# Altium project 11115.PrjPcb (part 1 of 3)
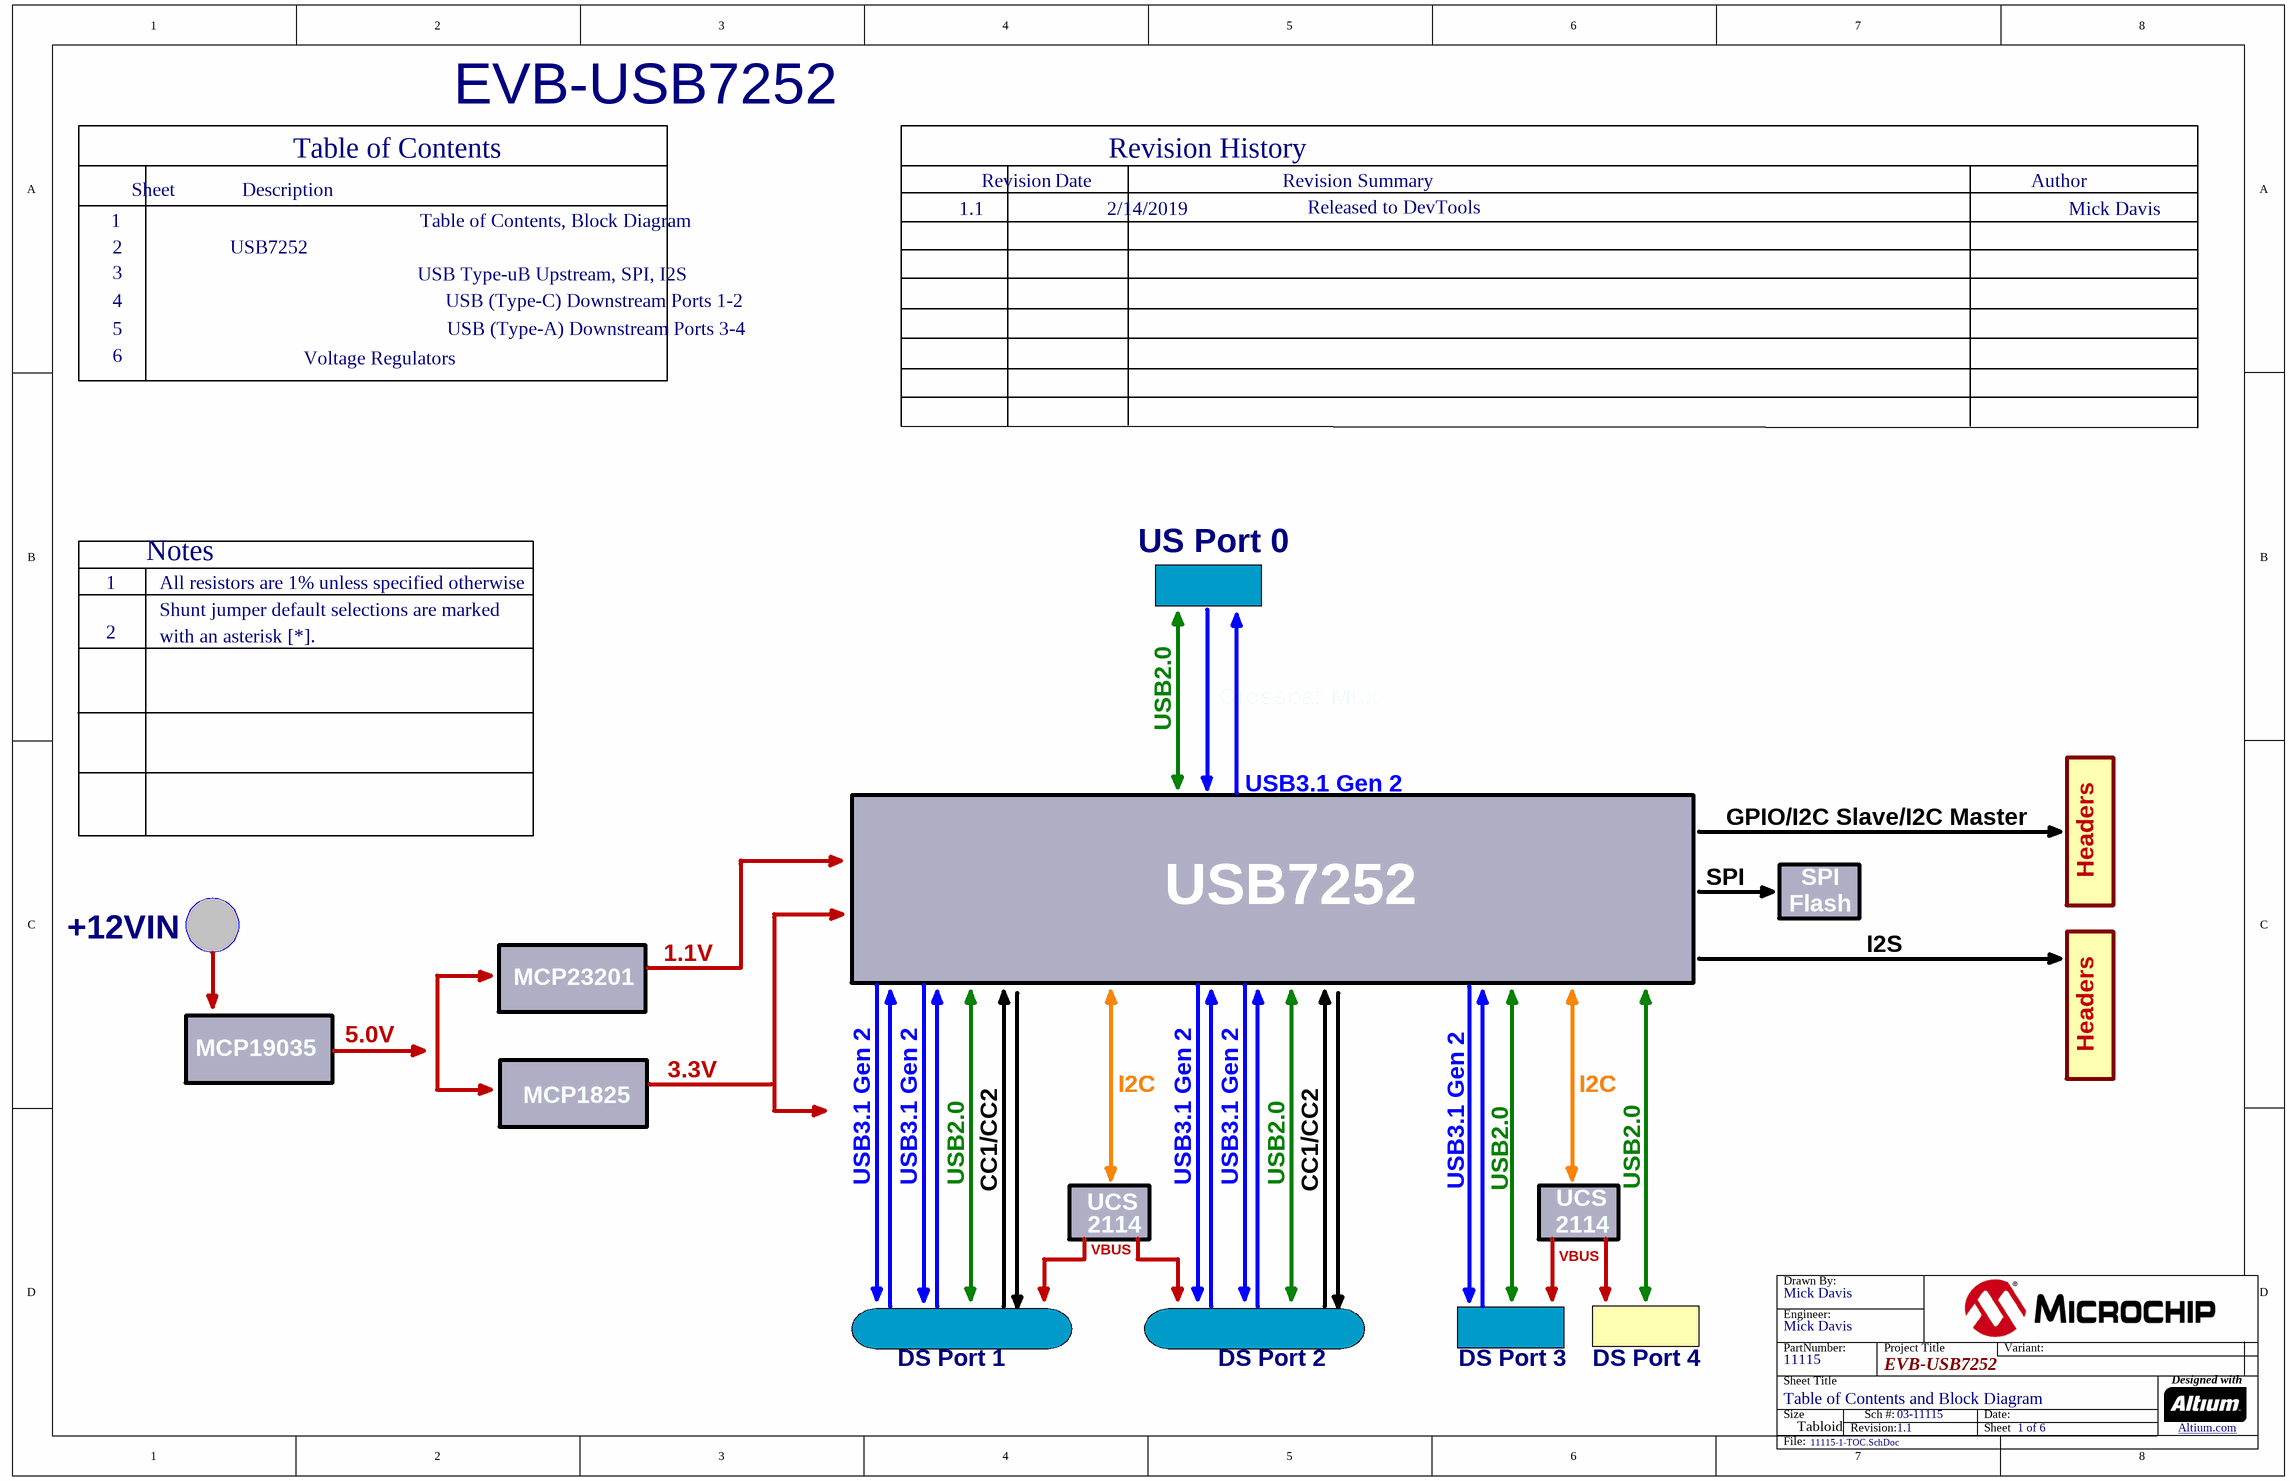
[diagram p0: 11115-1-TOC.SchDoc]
ProjectPCBNumber: 11115; SheetTotal: 6; Revision: 1.1; ProjectTitle: EVB-USB7252; ProjectRevisionSCH: 1.1; ProjectRevisionFAB: 1.1; ProjectRevisionASSY: 1.1; ProjectRevisionART: 1.1; ProjectPCBAssyNumber: 11115; ProjectPartNumber: 11115; ProjectEngineer: Mick Davis; ProjectDrawnBy: Mick Davis; ProjectBoardNumber: 11115; ProjectBoardLabel: 11115; PartNumber: 11115
6 sheets, 332 parts. Net scope: flat (ports and power ports of the same name join across sheets).
Board file: 11115.PcbDoc
Sheets:
  11115-1-TOC.SchDoc
  11115-2-USB7252.SchDoc
  11115-3-USB-B-Upstream.SchDoc
  11115-4-USB-C Downstream 1-2.SchDoc
  11115-5-USB-A Downstream 3-4.SchDoc
  11115-6-Voltage_Regulators.SchDoc

## Sheet 11115-1-TOC.SchDoc
size Tabloid; CompanyName: Microchip Technology Inc.; Organization: Microchip Technology; Address1: 2355 West Chandler Blvd.; Address2: Chandler, AZ  85224; Address4: USA; Revision: 1.0; SheetNumber: 1; SheetTotal: 6; SheetTitle: Table of Contents and Block Diagram

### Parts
(Parts that share a designator on the sheet are numbered #1, #2 ... from top to bottom, then left to right.)
?#1  (no value)  (graphical)

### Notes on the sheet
- Table of Contents
- Revision History
- 1
- Sheet
- Description
- Table of Contents, Block Diagram
- 1.1
- Revision
- Date
- 2/14/2019
- Revision Summary
- Released to DevTools
- Author
- Mick Davis
- 2
- 3
- USB7252
- USB Type-uB Upstream, SPI, I2S
- 4
- 5
- 6
- Voltage Regulators
- USB (Type-C) Downstream Ports 1-2
- USB (Type-A) Downstream Ports 3-4
- Notes
- US Port 0
- All resistors are 1% unless specified otherwise
- Shunt jumper default selections are marked
- with an asterisk [*].
- USB2.0
- Crossbar Mux
- USB3.1 Gen 2
- GPIO/I2C Slave/I2C Master
- SPI
- Headers
- +12VIN
- 1.1V
- Flash
- I2S
- MCP23201
- MCP19035
- 5.0V
- 3.3V
- I2C
- MCP1825
- CC1/CC2
- UCS
- 2114
- VBUS
- DS Port 1
- DS Port 2
- DS Port 3
- DS Port 4

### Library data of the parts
?#1 = Title Block Tabloid

## Sheet 11115-2-USB7252.SchDoc
size Tabloid; CompanyName: Microchip Technology Inc.; Organization: Microchip Technology; Address1: 2355 West Chandler Blvd.; Address2: Chandler, AZ  85224; Address4: USA; SheetNumber: 2; SheetTotal: 6; SheetTitle: USB7252
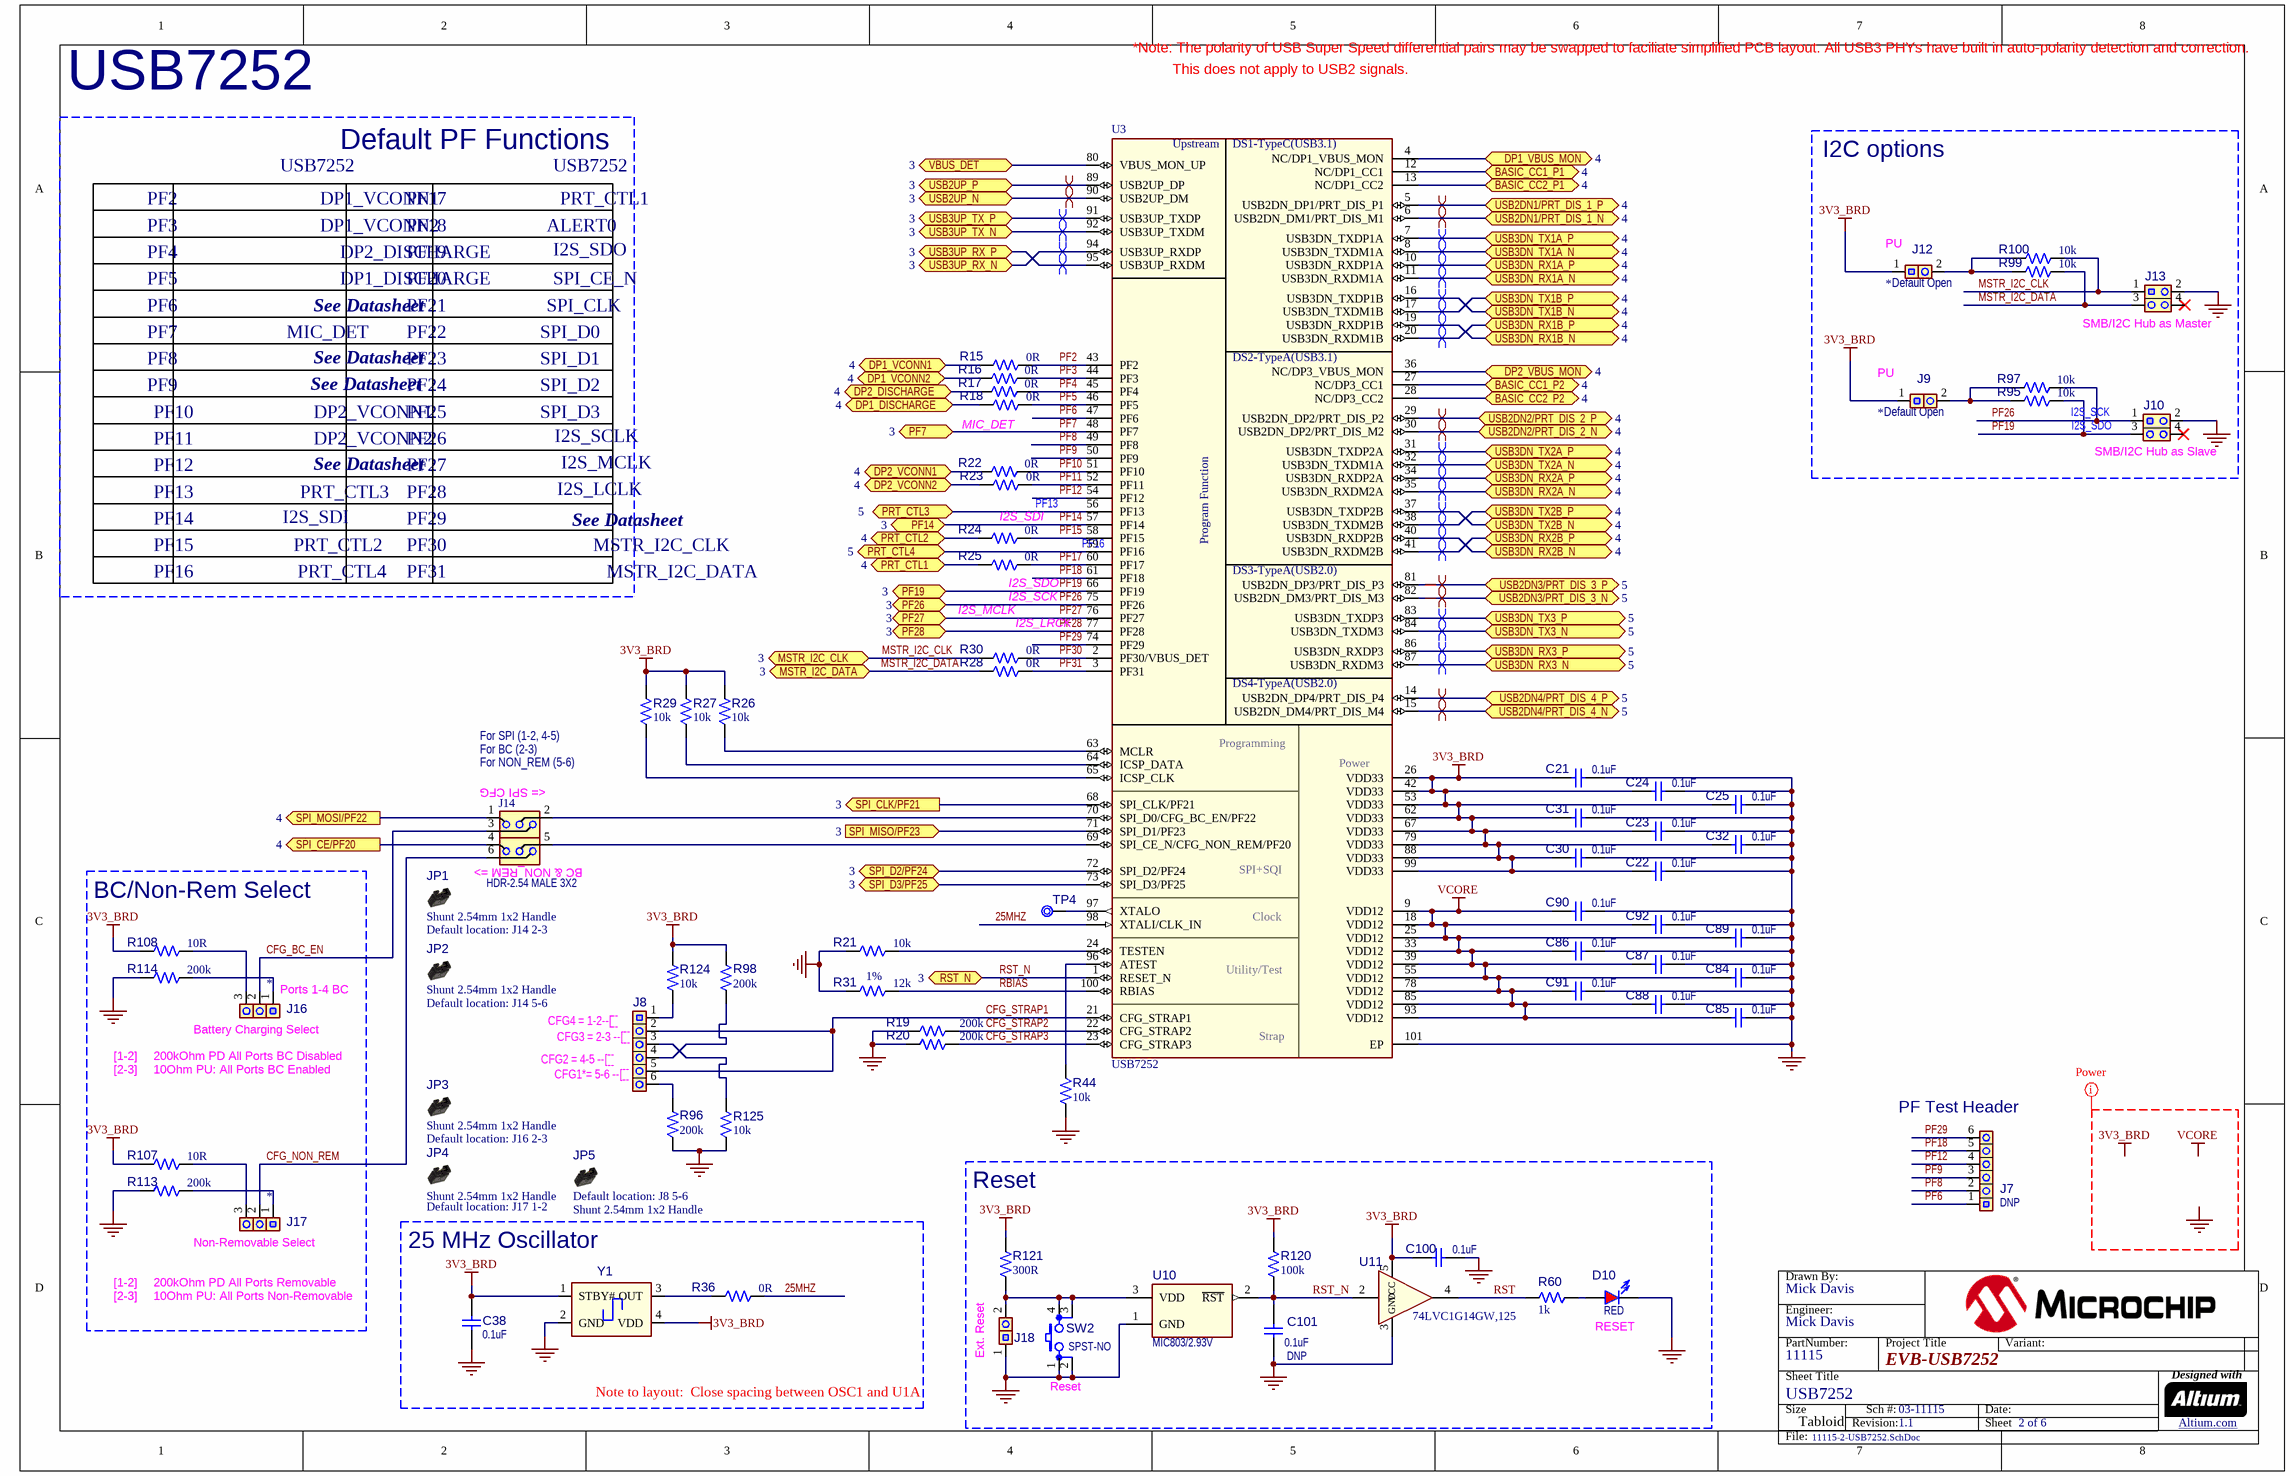
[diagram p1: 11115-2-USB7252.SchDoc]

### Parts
(Parts that share a designator on the sheet are numbered #1, #2 ... from top to bottom, then left to right.)
?#2  (no value)  (graphical)
C21  value 0.1uF  [CAP_C_0402]  (hidden comment: Capacitor NP)
C22  value 0.1uF  [CAP_C_0402]  (hidden comment: Capacitor NP)
C23  value 0.1uF  [CAP_C_0402]  (hidden comment: Capacitor NP)
C24  value 0.1uF  [CAP_C_0402]  (hidden comment: Capacitor NP)
C25  value 0.1uF  [CAP_C_0402]  (hidden comment: Capacitor NP)
C30  value 0.1uF  [CAP_C_0402]  (hidden comment: Capacitor NP)
C31  value 0.1uF  [CAP_C_0402]  (hidden comment: Capacitor NP)
C32  value 0.1uF  [CAP_C_0402]  (hidden comment: Capacitor NP)
C38  value 0.1uF  [CAP_C_0402]  (hidden comment: Capacitor NP)
C84  value 0.1uF  [CAP_C_0402]  (hidden comment: Capacitor NP)
C85  value 0.1uF  [CAP_C_0402]  (hidden comment: Capacitor NP)
C86  value 0.1uF  [CAP_C_0402]  (hidden comment: Capacitor NP)
C87  value 0.1uF  [CAP_C_0402]  (hidden comment: Capacitor NP)
C88  value 0.1uF  [CAP_C_0402]  (hidden comment: Capacitor NP)
C89  value 0.1uF  [CAP_C_0402]  (hidden comment: Capacitor NP)
C90  value 0.1uF  [CAP_C_0402]  (hidden comment: Capacitor NP)
C91  value 0.1uF  [CAP_C_0402]  (hidden comment: Capacitor NP)
C92  value 0.1uF  [CAP_C_0402]  (hidden comment: Capacitor NP)
C100  value 0.1uF  [CAP_C_0402]  (hidden comment: Capacitor NP)
C101  value 0.1uF  Populated: DNP  [CAP_C_0402]  (hidden comment: Capacitor NP)
D10  value RED  [LED_0603_RED]  (hidden comment: LED_red)
J7  Populated: DNP  [HDR_M_2.54_1x6]  (hidden comment: Header 1x6)
J8  Header 1x6  [HDR_M_2.54_1x6]  (value not drawn)
J9  Header 1x2  [HDR_M_2.54_1x2]  (value not drawn)
J10  Header 2x2  [HDR_M_2.54_2x2]  (value not drawn)
J12  Header 1x2  [HDR_M_2.54_1x2]  (value not drawn)
J13  Header 2x2  [HDR_M_2.54_2x2]  (value not drawn)
J14  value HDR-2.54 MALE 3X2  [CON_HDR_2.54_3X2]  (hidden comment: Header 3X2)
J16  Header 1x3  [HDR_M_2.54_1x3]  (value not drawn)
J17  Header 1x3  [HDR_M_2.54_1x3]  (value not drawn)
J18  Header 1x2  [HDR_M_2.54_1x2]  (value not drawn)
JP1  value Shunt 2.54mm 1x2 Handle  DefaultLocation: Default location: J14 2-3  [Jumper_W_Handle_Mechanical]  (hidden comment: Jumper Mechanical)  (mechanical)
JP2  value Shunt 2.54mm 1x2 Handle  DefaultLocation: Default location: J14 5-6  [Jumper_W_Handle_Mechanical]  (hidden comment: Jumper Mechanical)  (mechanical)
JP3  value Shunt 2.54mm 1x2 Handle  DefaultLocation: Default location: J16 2-3  [Jumper_W_Handle_Mechanical]  (hidden comment: Jumper Mechanical)  (mechanical)
JP4  value Shunt 2.54mm 1x2 Handle  DefaultLocation: Default location: J17 1-2  [Jumper_W_Handle_Mechanical]  (hidden comment: Jumper Mechanical)  (mechanical)
JP5  value Shunt 2.54mm 1x2 Handle  DefaultLocation: Default location: J8 5-6  [Jumper_W_Handle_Mechanical]  (hidden comment: Jumper Mechanical)  (mechanical)
R15  0R  [RES_C_0603]
R16  0R  [RES_C_0603]
R17  0R  [RES_C_0603]
R18  0R  [RES_C_0603]
R19  value 200k  [RES_C_0603]  (hidden comment: Resistor)
R20  value 200k  [RES_C_0603]  (hidden comment: Resistor)
R21  value 10k  [RES_C_0603]  (hidden comment: Resistor)
R22  0R  [RES_C_0603]
R23  0R  [RES_C_0603]
R24  0R  [RES_C_0603]
R25  0R  [RES_C_0603]
R26  value 10k  [RES_C_0603]  (hidden comment: Resistor)
R27  value 10k  [RES_C_0603]  (hidden comment: Resistor)
R28  0R  [RES_C_0603]
R29  value 10k  [RES_C_0603]  (hidden comment: Resistor)
R30  0R  [RES_C_0603]
R31  value 12k  Tolerance: 1%  [RES_C_0603]  (hidden comment: Resistor)
R36  value 0R  [RES_C_0603]  (hidden comment: Resistor)
R44  value 10k  [RES_C_0603]  (hidden comment: Resistor)
R60  value 1k  [RES_C_0603]  (hidden comment: Resistor)
R95  value 10k  [RES_C_0603]  (hidden comment: Resistor)
R96  value 200k  [RES_C_0603]  (hidden comment: Resistor)
R97  value 10k  [RES_C_0603]  (hidden comment: Resistor)
R98  value 200k  [RES_C_0603]  (hidden comment: Resistor)
R99  value 10k  [RES_C_0603]  (hidden comment: Resistor)
R100  value 10k  [RES_C_0603]  (hidden comment: Resistor)
R107  value 10R  [RES_C_0603]  (hidden comment: Resistor)
R108  value 10R  [RES_C_0603]  (hidden comment: Resistor)
R113  value 200k  [RES_C_0603]  (hidden comment: Resistor)
R114  value 200k  [RES_C_0603]  (hidden comment: Resistor)
R120  value 100k  [RES_C_0603]  (hidden comment: Resistor)
R121  value 300R  [RES_C_0603]  (hidden comment: Resistor)
R124  value 10k  [RES_C_0603]  (hidden comment: Resistor)
R125  value 10k  [RES_C_0603]  (hidden comment: Resistor)
SW2  value SPST-NO  [SW_TACT_SMD_CK_PTS810SJM]  (hidden comment: Switch 4 Pin)
TP4  Test Point No BOM  [CON_TP_22P11_TH]  (value not drawn)  (no BOM)
U3  value USB7252  [TQFN-100_12x12_EP8.0]  (hidden comment: USB7252 VQFN-100)
U10  value MIC803/2.93V  [SOT-23-3]  (hidden comment: MIC803 SOT-23-3)
U11  74LVC1G14GW,125  [SC-70-5]
Y1  OSCILLATOR_4P_nSTBY  [OSCILLATOR_CDFN_L2.5W2.0H0.85]  (value not drawn)

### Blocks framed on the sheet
I2C options: J9 J10 J12 J13 R95 R97 R99 R100
BC/Non-Rem Select: J16 J17 R107 R108 R113 R114
Reset: C100 C101 D10 J18 R60 R120 R121 SW2 U10 U11
25 MHz Oscillator: C38 R36 Y1

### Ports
BASIC_CC1_P1 (bidir, see 4), BASIC_CC1_P2 (bidir, see 4), BASIC_CC2_P1 (bidir, see 4), BASIC_CC2_P2 (bidir, see 4), DP1_DISCHARGE (bidir, see 4), DP1_VBUS_MON (bidir, see 4), DP1_VCONN1 (bidir, see 4), DP1_VCONN2 (bidir, see 4), DP2_DISCHARGE (bidir, see 4), DP2_VBUS_MON (bidir, see 4), DP2_VCONN1 (bidir, see 4), DP2_VCONN2 (bidir, see 4), MSTR_I2C_CLK (bidir, see 3), MSTR_I2C_DATA (bidir, see 3), PF7 (bidir, see 3), PF14 (bidir, see 3), PF19 (bidir, see 3), PF26 (bidir, see 3), PF27 (bidir, see 3), PF28 (bidir, see 3), PRT_CTL1 (bidir, see 4), PRT_CTL2 (bidir, see 4), PRT_CTL3 (bidir, see 5), PRT_CTL4 (bidir, see 5), RST_N (bidir, see 3), SPI_CE/PF20 (out, see 4), SPI_CLK/PF21 (out, see 3), SPI_D2/PF24 (bidir, see 3), SPI_D3/PF25 (bidir, see 3), SPI_MISO/PF23 (in, see 3), SPI_MOSI/PF22 (out, see 4), USB2DN1/PRT_DIS_1_N (bidir, see 4), USB2DN1/PRT_DIS_1_P (bidir, see 4), USB2DN2/PRT_DIS_2_N (bidir, see 4), USB2DN2/PRT_DIS_2_P (bidir, see 4), USB2DN3/PRT_DIS_3_N (bidir, see 5), USB2DN3/PRT_DIS_3_P (bidir, see 5), USB2DN4/PRT_DIS_4_N (bidir, see 5), USB2DN4/PRT_DIS_4_P (bidir, see 5), USB2UP_N (bidir, see 3), USB2UP_P (bidir, see 3), USB3DN_RX1A_N (bidir, see 4), USB3DN_RX1A_P (bidir, see 4), USB3DN_RX1B_N (bidir, see 4), USB3DN_RX1B_P (bidir, see 4), USB3DN_RX2A_N (bidir, see 4), USB3DN_RX2A_P (bidir, see 4), USB3DN_RX2B_N (bidir, see 4), USB3DN_RX2B_P (bidir, see 4), USB3DN_RX3_N (bidir, see 5), USB3DN_RX3_P (bidir, see 5), USB3DN_TX1A_N (bidir, see 4), USB3DN_TX1A_P (bidir, see 4), USB3DN_TX1B_N (bidir, see 4), USB3DN_TX1B_P (bidir, see 4), USB3DN_TX2A_N (bidir, see 4), USB3DN_TX2A_P (bidir, see 4), USB3DN_TX2B_N (bidir, see 4), USB3DN_TX2B_P (bidir, see 4), USB3DN_TX3_N (bidir, see 5), USB3DN_TX3_P (bidir, see 5), USB3UP_RX_N (bidir, see 3), USB3UP_RX_P (bidir, see 3), USB3UP_TX_N (bidir, see 3), USB3UP_TX_P (bidir, see 3), VBUS_DET (bidir, see 3)

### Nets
3V3_BRD: C21.1 C22.1 C23.1 C24.1 C25.1 C30.1 C31.1 C32.1 C38.2 C100.1 J9.1 J12.1 R26.2 R27.2 R29.2 R98.1 R107.1 R108.1 R120.2 R121.2 R124.1 U3.26(VDD33) U3.42(VDD33) U3.53(VDD33) U3.62(VDD33) U3.67(VDD33) U3.79(VDD33) U3.88(VDD33) U3.99(VDD33) U11.5(VCC) Y1.1(STBY#) Y1.4(VDD)
GND: C21.2 C22.2 C23.2 C24.2 C25.2 C30.2 C31.2 C32.2 C38.1 C84.2 C85.2 C86.2 C87.2 C88.2 C89.2 C90.2 C91.2 C92.2 C100.2 C101.1 D10.2(K) J10.2 J13.2 J18.1 R19.2 R20.2 R21.2 R31.1 R44.2 R96.2 R113.1 R114.1 R125.2 SW2.1 SW2.2 U3.101(EP) U10.1(GND) U11.3(GND) Y1.2(GND)
VCORE: C84.1 C85.1 C86.1 C87.1 C88.1 C89.1 C90.1 C91.1 C92.1 U3.9(VDD12) U3.18(VDD12) U3.25(VDD12) U3.33(VDD12) U3.39(VDD12) U3.55(VDD12) U3.78(VDD12) U3.85(VDD12) U3.93(VDD12)
25MHZ: R36.2 U3.98(XTALI/CLK_IN)
BASIC_CC1_P1: U3.12(NC/DP1_CC1) ; port BASIC_CC1_P1
BASIC_CC1_P2: U3.27(NC/DP3_CC1) ; port BASIC_CC1_P2
BASIC_CC2_P1: U3.13(NC/DP1_CC2) ; port BASIC_CC2_P1
BASIC_CC2_P2: U3.28(NC/DP3_CC2) ; port BASIC_CC2_P2
CFG_BC_EN: J14.3 J16.2
CFG_NON_REM: J14.6 J17.2
CFG_STRAP1: J8.2 J8.5 U3.21(CFG_STRAP1)
CFG_STRAP2: R19.1 U3.22(CFG_STRAP2)
CFG_STRAP3: R20.1 U3.23(CFG_STRAP3)
DP1_DISCHARGE: R18.1 ; port DP1_DISCHARGE
DP1_VBUS_MON: U3.4(NC/DP1_VBUS_MON) ; port DP1_VBUS_MON
DP1_VCONN1: R15.1 ; port DP1_VCONN1
DP1_VCONN2: R16.1 ; port DP1_VCONN2
DP2_DISCHARGE: R17.1 ; port DP2_DISCHARGE
DP2_VBUS_MON: U3.36(NC/DP3_VBUS_MON) ; port DP2_VBUS_MON
DP2_VCONN1: R22.1 ; port DP2_VCONN1
DP2_VCONN2: R23.1 ; port DP2_VCONN2
MSTR_I2C_CLK: J13.1 R30.1 R100.1 ; port MSTR_I2C_CLK
MSTR_I2C_DATA: J13.3 R28.1 R99.1 ; port MSTR_I2C_DATA
PF2: R15.2 U3.43(PF2)
PF3: R16.2 U3.44(PF3)
PF4: R17.2 U3.45(PF4)
PF5: R18.2 U3.46(PF5)
PF6: J7.1 U3.47(PF6)
PF7: U3.48(PF7) ; port PF7
PF8: J7.2 U3.49(PF8)
PF9: J7.3 U3.50(PF9)
PF10: R22.2 U3.51(PF10)
PF11: R23.2 U3.52(PF11)
PF12: J7.4 U3.54(PF12)
PF14: U3.57(PF14) ; port PF14
PF15: R24.2 U3.58(PF15)
PF17: R25.2 U3.60(PF17)
PF18: J7.5 U3.61(PF18)
PF19: J10.3 R95.1 U3.66(PF19) ; port PF19
PF26: J10.1 R97.1 U3.75(PF26) ; port PF26
PF27: U3.76(PF27) ; port PF27
PF28: U3.77(PF28) ; port PF28
PF29: J7.6 U3.74(PF29)
PF30: R30.2 U3.2(PF30/VBUS_DET)
PF31: R28.2 U3.3(PF31)
PRT_CTL1: R25.1 ; port PRT_CTL1
PRT_CTL2: R24.1 ; port PRT_CTL2
PRT_CTL3: U3.56(PF13) ; port PRT_CTL3
PRT_CTL4: U3.59(PF16) ; port PRT_CTL4
RBIAS: R31.2 U3.100(RBIAS)
RST: R60.1 U11.4(Y)
RST_N: C101.2 R120.1 U3.1(RESET_N) U10.2(~{RST}) U11.2(A) ; port RST_N
SPI_CE/PF20: J14.4 ; port SPI_CE/PF20
SPI_CLK/PF21: U3.68(SPI_CLK/PF21) ; port SPI_CLK/PF21
SPI_D2/PF24: U3.72(SPI_D2/PF24) ; port SPI_D2/PF24
SPI_D3/PF25: U3.73(SPI_D3/PF25) ; port SPI_D3/PF25
SPI_MISO/PF23: U3.71(SPI_D1/PF23) ; port SPI_MISO/PF23
SPI_MOSI/PF22: J14.1 ; port SPI_MOSI/PF22
USB2DN1/PRT_DIS_1_N: U3.6(USB2DN_DM1/PRT_DIS_M1) ; port USB2DN1/PRT_DIS_1_N
USB2DN1/PRT_DIS_1_P: U3.5(USB2DN_DP1/PRT_DIS_P1) ; port USB2DN1/PRT_DIS_1_P
USB2DN2/PRT_DIS_2_N: U3.30(USB2DN_DP2/PRT_DIS_M2) ; port USB2DN2/PRT_DIS_2_N
USB2DN2/PRT_DIS_2_P: U3.29(USB2DN_DP2/PRT_DIS_P2) ; port USB2DN2/PRT_DIS_2_P
USB2DN3/PRT_DIS_3_N: U3.82(USB2DN_DM3/PRT_DIS_M3) ; port USB2DN3/PRT_DIS_3_N
USB2DN3/PRT_DIS_3_P: U3.81(USB2DN_DP3/PRT_DIS_P3) ; port USB2DN3/PRT_DIS_3_P
USB2DN4/PRT_DIS_4_N: U3.15(USB2DN_DM4/PRT_DIS_M4) ; port USB2DN4/PRT_DIS_4_N
USB2DN4/PRT_DIS_4_P: U3.14(USB2DN_DP4/PRT_DIS_P4) ; port USB2DN4/PRT_DIS_4_P
USB2UP_N: U3.90(USB2UP_DM) ; port USB2UP_N
USB2UP_P: U3.89(USB2UP_DP) ; port USB2UP_P
USB3DN_RX1A_N: U3.11(USB3DN_RXDM1A) ; port USB3DN_RX1A_N
USB3DN_RX1A_P: U3.10(USB3DN_RXDP1A) ; port USB3DN_RX1A_P
USB3DN_RX1B_N: U3.19(USB3DN_RXDP1B) ; port USB3DN_RX1B_N
USB3DN_RX1B_P: U3.20(USB3DN_RXDM1B) ; port USB3DN_RX1B_P
USB3DN_RX2A_N: U3.35(USB3DN_RXDM2A) ; port USB3DN_RX2A_N
USB3DN_RX2A_P: U3.34(USB3DN_RXDP2A) ; port USB3DN_RX2A_P
USB3DN_RX2B_N: U3.40(USB3DN_RXDP2B) ; port USB3DN_RX2B_N
USB3DN_RX2B_P: U3.41(USB3DN_RXDM2B) ; port USB3DN_RX2B_P
USB3DN_RX3_N: U3.87(USB3DN_RXDM3) ; port USB3DN_RX3_N
USB3DN_RX3_P: U3.86(USB3DN_RXDP3) ; port USB3DN_RX3_P
USB3DN_TX1A_N: U3.8(USB3DN_TXDM1A) ; port USB3DN_TX1A_N
USB3DN_TX1A_P: U3.7(USB3DN_TXDP1A) ; port USB3DN_TX1A_P
USB3DN_TX1B_N: U3.16(USB3DN_TXDP1B) ; port USB3DN_TX1B_N
USB3DN_TX1B_P: U3.17(USB3DN_TXDM1B) ; port USB3DN_TX1B_P
USB3DN_TX2A_N: U3.32(USB3DN_TXDM1A) ; port USB3DN_TX2A_N
USB3DN_TX2A_P: U3.31(USB3DN_TXDP2A) ; port USB3DN_TX2A_P
USB3DN_TX2B_N: U3.37(USB3DN_TXDP2B) ; port USB3DN_TX2B_N
USB3DN_TX2B_P: U3.38(USB3DN_TXDM2B) ; port USB3DN_TX2B_P
USB3DN_TX3_N: U3.84(USB3DN_TXDM3) ; port USB3DN_TX3_N
USB3DN_TX3_P: U3.83(USB3DN_TXDP3) ; port USB3DN_TX3_P
USB3UP_RX_N: U3.94(USB3UP_RXDP) ; port USB3UP_RX_N
USB3UP_RX_P: U3.95(USB3UP_RXDM) ; port USB3UP_RX_P
USB3UP_TX_N: U3.92(USB3UP_TXDM) ; port USB3UP_TX_N
USB3UP_TX_P: U3.91(USB3UP_TXDP) ; port USB3UP_TX_P
VBUS_DET: U3.80(VBUS_MON_UP) ; port VBUS_DET
NetD10_1: D10.1(A) R60.2
NetJ8_1: J8.1 R124.2
NetJ8_3: J8.3 R125.1
NetJ8_4: J8.4 R98.2
NetJ8_6: J8.6 R96.1
NetJ9_2: J9.2 R95.2 R97.2
NetJ12_2: J12.2 R99.2 R100.2
NetJ14_2: J14.2 U3.70(SPI_D0/CFG_BC_EN/PF22)
NetJ14_5: J14.5 U3.69(SPI_CE_N/CFG_NON_REM/PF20)
NetJ16_1: J16.1 R114.2
NetJ16_3: J16.3 R108.2
NetJ17_1: J17.1 R113.2
NetJ17_3: J17.3 R107.2
NetJ18_2: J18.2 R121.1 SW2.3 SW2.4 U10.3(VDD)
NetR21_1: R21.1 U3.24(TESTEN)
NetR26_1: R26.1 U3.63(MCLR)
NetR27_1: R27.1 U3.64(ICSP_DATA)
NetR29_1: R29.1 U3.65(ICSP_CLK)
NetR36_1: R36.1 Y1.3(OUT)
NetR44_1: R44.1 U3.96(ATEST)
NetTP4_1: TP4.1 U3.97(XTALO)

Not connected (* = marked no-connect by the designer): J10 4*; J13 4*; U11 1(NC)

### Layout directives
differential pair; net class USB3.: USB3DN_RX1A_N, USB3DN_RX1A_P, USB3DN_RX1B_N, USB3DN_RX1B_P, USB3DN_RX2A_N, USB3DN_RX2A_P, USB3DN_RX2B_N, USB3DN_RX2B_P, USB3DN_RX3_N, USB3DN_RX3_P, USB3DN_TX1A_N, USB3DN_TX1A_P, USB3DN_TX1B_N, USB3DN_TX1B_P, USB3DN_TX2A_N, USB3DN_TX2A_P, USB3DN_TX2B_N, USB3DN_TX2B_P, USB3DN_TX3_N, USB3DN_TX3_P, USB3UP_RX_N, USB3UP_RX_P, USB3UP_TX_N, USB3UP_TX_P
differential pair; net class USB2.: USB2DN1/PRT_DIS_1_N, USB2DN1/PRT_DIS_1_P, USB2DN2/PRT_DIS_2_N, USB2DN2/PRT_DIS_2_P, USB2DN3/PRT_DIS_3_N, USB2DN3/PRT_DIS_3_P, USB2DN4/PRT_DIS_4_N, USB2DN4/PRT_DIS_4_P, USB2UP_N, USB2UP_P
net class Power: 3V3_BRD, GND, VCORE

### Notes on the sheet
- USB7252
- *Note: The polarity of USB Super Speed differential pairs may be swapped to faciliate simplified PCB layout. All USB3 PHYs have built in auto-polarity detection and correction.
- This does not apply to USB2 signals.
- Default PF Functions
- PF3
- PF2
- DP1_VCONN1
- DP1_VCONN2
- PF17
- PF18
- ALERT0
- PRT_CTL1
- PF4
- PF5
- DP2_DISCHARGE
- DP1_DISCHARGE
- PF19
- PF20
- SPI_CE_N
- I2S_SDO
- (near J12) PU
- (near J12) *
- (near J12) Default Open
- PF7
- PF8
- PF6
- MIC_DET
- See Datasheet
- PF21
- PF23
- PF22
- SPI_D0
- SPI_D1
- SPI_CLK
- (near J13) SMB/I2C Hub as Master
- PF9
- PF10
- DP2_VCONN1
- PF24
- PF25
- SPI_D2
- SPI_D3
- (near R18) MIC_DET
- (near J9) PU
- (near J9) *
- (near J9) Default Open
- (near R95) I2S_SCK
- PF11
- PF12
- PF13
- PRT_CTL3
- DP2_VCONN2
- PF26
- PF27
- PF28
- I2S_SCLK
- I2S_LCLK
- I2S_MCLK
- (near J10) SMB/I2C Hub as Slave
- PF15
- PF14
- I2S_SDI
- PRT_CTL2
- PF30
- PF29
- MSTR_I2C_CLK
- (near R24) I2S_SDI
- PF16
- PRT_CTL4
- PF31
- MSTR_I2C_DATA
- (near R25) I2S_SCK
- (near R25) I2S_SDO
- I2S_LRCK
- For SPI (1-2, 4-5)
- For BC (2-3)
- For NON_REM (5-6)
- (near J14) <= SPI CFG
- (near J14) BC & NON_REM =>
- (near J16) *
- (near J16) Ports 1-4 BC
- (near J8) CFG4 = 1-2--[
- (near J8) --
- [1-2]
- [2-3]
- 10Ohm PU: All Ports BC Enabled
- 200kOhm PD All Ports BC Disabled
- (near J16) Battery Charging Select
- (near J8) CFG2 = 4-5 --[
- (near J8) CFG1*= 5-6 --[
- (near J8) CFG3 = 2-3 --[
- (near J7) PF Test Header
- (near J17) *
- 200kOhm PD All Ports Removable
- (near J17) Non-Removable Select
- 10Ohm PU: All Ports Non-Removable
- Ext. Reset
- RESET
- Note to layout:  Close spacing between OSC1 and U1A
- (near SW2) Reset
- Labels drawn without touching a wire or pin: 3V3_BRD, GND, VCORE

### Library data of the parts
?#2 = Title Block Tabloid
C21-C25 C30-C32 C38 C84-C92 C100 = CAP1337: Capacitor; Manufacturer 1: TDK Corporation; Manufacturer Part Number 1: CGA2B3X7R1V104K050BB; Voltage: 35V; Description_: CAP CER 0.1uF 35V 10% X7R SMD 0402; Dev Tools Status: Design; Tolerance: 10%; Temperature Coeffcient: X7R; Type: Ceramic; Owner: Sam Charles; Populated: YES
C101 = CAP1337: Capacitor; Manufacturer 1: TDK Corporation; Manufacturer Part Number 1: CGA2B3X7R1V104K050BB; Voltage: 35V; Description_: CAP CER 0.1uF 35V 10% X7R SMD 0402; Dev Tools Status: Design; Tolerance: 10%; Temperature Coeffcient: X7R; Type: Ceramic; Owner: Sam Charles
D10 = LED1073: LED; Manufacturer 1: Lite-On Inc.; Manufacturer Part Number 1: LTST-C191KRKT; Description_: DIO RED 2V 20mA 54mcd CLEAR SMD 0603; Dev Tools Status: Production; Type: LED Single; Forward Current: 20mA; Owner: Sompoch Loboonlert; Populated: YES
J7 = CON0438: Manufacturer 1: Sullins; Manufacturer Part Number 1: PEC06SAAN; Value: HDR-2.54 Male 1x6; Description_: CON HDR-2.54 Male 1x6 Tin 5.84MH TH VERT; Dev Tools Status: Production; Current: 3A
J8 = CON0438: Manufacturer 1: Sullins; Manufacturer Part Number 1: PEC06SAAN; Value: HDR-2.54 Male 1x6; Description_: CON HDR-2.54 Male 1x6 Tin 5.84MH TH VERT; Dev Tools Status: Production; Current: 3A; Populated: YES
J9 J12 J18 = CON1108: Manufacturer 1: FCI; Manufacturer Part Number 1: 77311-118-02LF; Value: HDR-2.54 Male 1x2; Description_: CON HDR-2.54 Male 1x2 Gold 5.84MH TH VERT; Dev Tools Status: Production; Owner: Bogdan P (M91398); Populated: Yes
J10 J13 = CON0464: Manufacturer 1: Samtec; Manufacturer Part Number 1: TSW-102-07-G-D; Value: HDR-2.54 Male 2x2; Description_: CON HDR-2.54 Male 2x2 Gold 5.84MH TH VERT; Dev Tools Status: Production; Populated: YES
J14 = CON1743: Manufacturer 1: Samtec Inc.; Manufacturer Part Number 1: TSW-102-07-G-T; Description_: CON HDR-2.54 Male 3x2 Gold 5.84MH TH VERT; Dev Tools Status: Design; Owner: Sam Charles; Populated: YES
J16 J17 = CON1105: Manufacturer 1: FCI; Manufacturer Part Number 1: 68000-103HLF; Value: HDR-2.54 Male 1x3; Description_: CON HDR-2.54 Male 1x3 Gold 5.84MH TH VERT; Dev Tools Status: Production; Owner: Bogdan P (M91398); Populated: Yes
JP1-JP5 = HW1008: Manufacturer 1: TE Connectivity AMP Connectors; Manufacturer Part Number 1: 880584-4; MCHP-ID: HW1008; Description_: MECH HW JUMPER 2.54mm 1x2 w/ Handle; Dev Tools Status: Production; Owner: Jairuz Agang-ang; Populated: MECH
R15-R18 R22-R25 R28 R30 = RSMT0001: Resistor; Manufacturer 1: NIC Components; Manufacturer Part Number 1: NRC06Z0TRF; Description_: RES TKF 0R 1/10W SMD 0603; Power: 1/10W; Populated: Yes
R19 R20 R96 R98 R113 R114 = RSMT0627: Manufacturer 1: Panasonic; Manufacturer Part Number 1: ERJ-3EKF2003V; Tolerance: 1%; Description_: RES TKF 200k 1% 1/10W SMD 0603; Dev Tools Status: Production; Voltage: 75V; Temperature Coeffcient: 100ppm/C; Power: 1/10W; Populated: Yes
R21 R26 R27 R29 R44 R95 R97 R99 R100 R124 R125 = RSMT0625: Manufacturer 1: ROHM; Manufacturer Part Number 1: MCR03EZPFX1002; Tolerance: 1%; Description_: RES TKF 10k 1% 1/10W SMD 0603; Voltage: 75V; Temperature Coeffcient: 100ppm/C; Power: 1/10W; Populated: Yes; Dev Tools Status: Production
R31 = RES1120: Manufacturer 1: Yageo; Manufacturer Part Number 1: RC0603FR-0712KL; Description_: RES TKF 12k 1% 1/10W SMD 0603; Voltage: 50V; Temperature Coeffcient: 100ppm/C; Power: 1/10W; Owner: Mihai T (M91442); Populated: Yes; Dev Tools Status: Production
R36 = RSMT0001: Manufacturer 1: Panasonic; Manufacturer Part Number 1: ERJ-3GSY0R00V; Description_: RES TKF 0R 1/10W SMD 0603; Dev Tools Status: Production; Power: 1/10W; Populated: Yes
R60 = RSMT0138: Manufacturer 1: Panasonic; Manufacturer Part Number 1: ERJ-3EKF1001V; Tolerance: 1%; Description_: RES TKF 1k 1% 1/10W SMD 0603; Voltage: 75V; Temperature Coeffcient: 100ppm/C; Power: 1/10W; Populated: Yes; Dev Tools Status: Production
R107 R108 = RSMT0456: Manufacturer 1: Panasonic; Manufacturer Part Number 1: ERJ-3EKF10R0V; Tolerance: 1%; Description_: RES TKF 10R 1% 1/10W SMD 0603; Dev Tools Status: Production; Voltage: 75V; Temperature Coeffcient: 100ppm/C; Power: 1/10W; Populated: Yes
R120 = RSMT0215: Manufacturer 1: Panasonic; Manufacturer Part Number 1: ERJ-3EKF1003V; Description_: RES TKF 100k 1% 1/10W SMD 0603; Voltage: 75V; Temperature Coeffcient: 100ppm/C; Power: 1/10W; Populated: Yes; Tolerance: 1%; Dev Tools Status: Production
R121 = RES1404: Manufacturer 1: Yageo; Manufacturer Part Number 1: RC0603FR-07300RL; Tolerance: 1%; Description_: RES TKF 300R 1% 1/10W SMD 0603; Dev Tools Status: Production; Temperature Coeffcient: 100ppm/C; Power: 1/10W; Owner: Henry de Villiers; Populated: YES
SW2 = SWITCH1072: Switch; Manufacturer 1: C&K Components; Manufacturer Part Number 1: PTS810 SJM 250 SMTR LFS; Description_: SWITCH TACT SPST 16V 50mA  PTS810 SJM 250 SMTR LFS SMD; Dev Tools Status: Design; Owner: Sam Charles; Voltage: 16V; Current: 50mA; Populated: YES
TP4 = CON2017: Test Point; Value: TP PAD .56mm; Description_: CON TP PAD PCB 0.56mm TH; Dev Tools Status: Design; Owner: Sam Charles; Populated: DNP
U3 = MIC8839: Manufacturer 1: Microchip Technology; Manufacturer Part Number 1: USB7252/KDX; Description_: MCHP INTERFACE USB 3.1 4 PORT CTLR HUB VQFN-100; Dev Tools Status: Design; Owner: Sam Charles; Populated: YES
U10 = MIC7416: Manufacturer 1: Microchip Technology; Manufacturer Part Number 1: MIC803-29D4VM3-TR; Description_: MCHP ANALOG SUPERVISOR 2.93V MIC803-29D4VM3-TR SOT-23-3; Dev Tools Status: Design; Owner: Sam Charles; Populated: YES
U11 = IC1251: Single Schmitt Trigger Inverter; Manufacturer 1: NXP; MCHP-ID: IC1251; Description_: 74LVC1G14GW,125  SCHMITT-TRG INVERTER; Dev Tools Status: Design; Owner: Ed Kennedy; Populated: YES
Y1 = MIC8253: Manufacturer 1: Microchip Technology; Manufacturer Part Number 1: DSC1001CI2-025.0000; Description_: MCHP CLOCK OSCILLATOR SINGLE 25MHZ DSC1001CI2-025.0000 CDFN-4; Dev Tools Status: Production; Value: 25MHz; Owner: Sam Charles; Populated: YES

## Sheet 11115-3-USB-B-Upstream.SchDoc
size Tabloid; CompanyName: Microchip Technology Inc.; Organization: Microchip Technology; Address1: 2355 West Chandler Blvd.; Address2: Chandler, AZ  85224; Address4: USA; SheetNumber: 3; SheetTotal: 6; SheetTitle: USB-B Upstream Port 0, SPI Flash, I2S Module
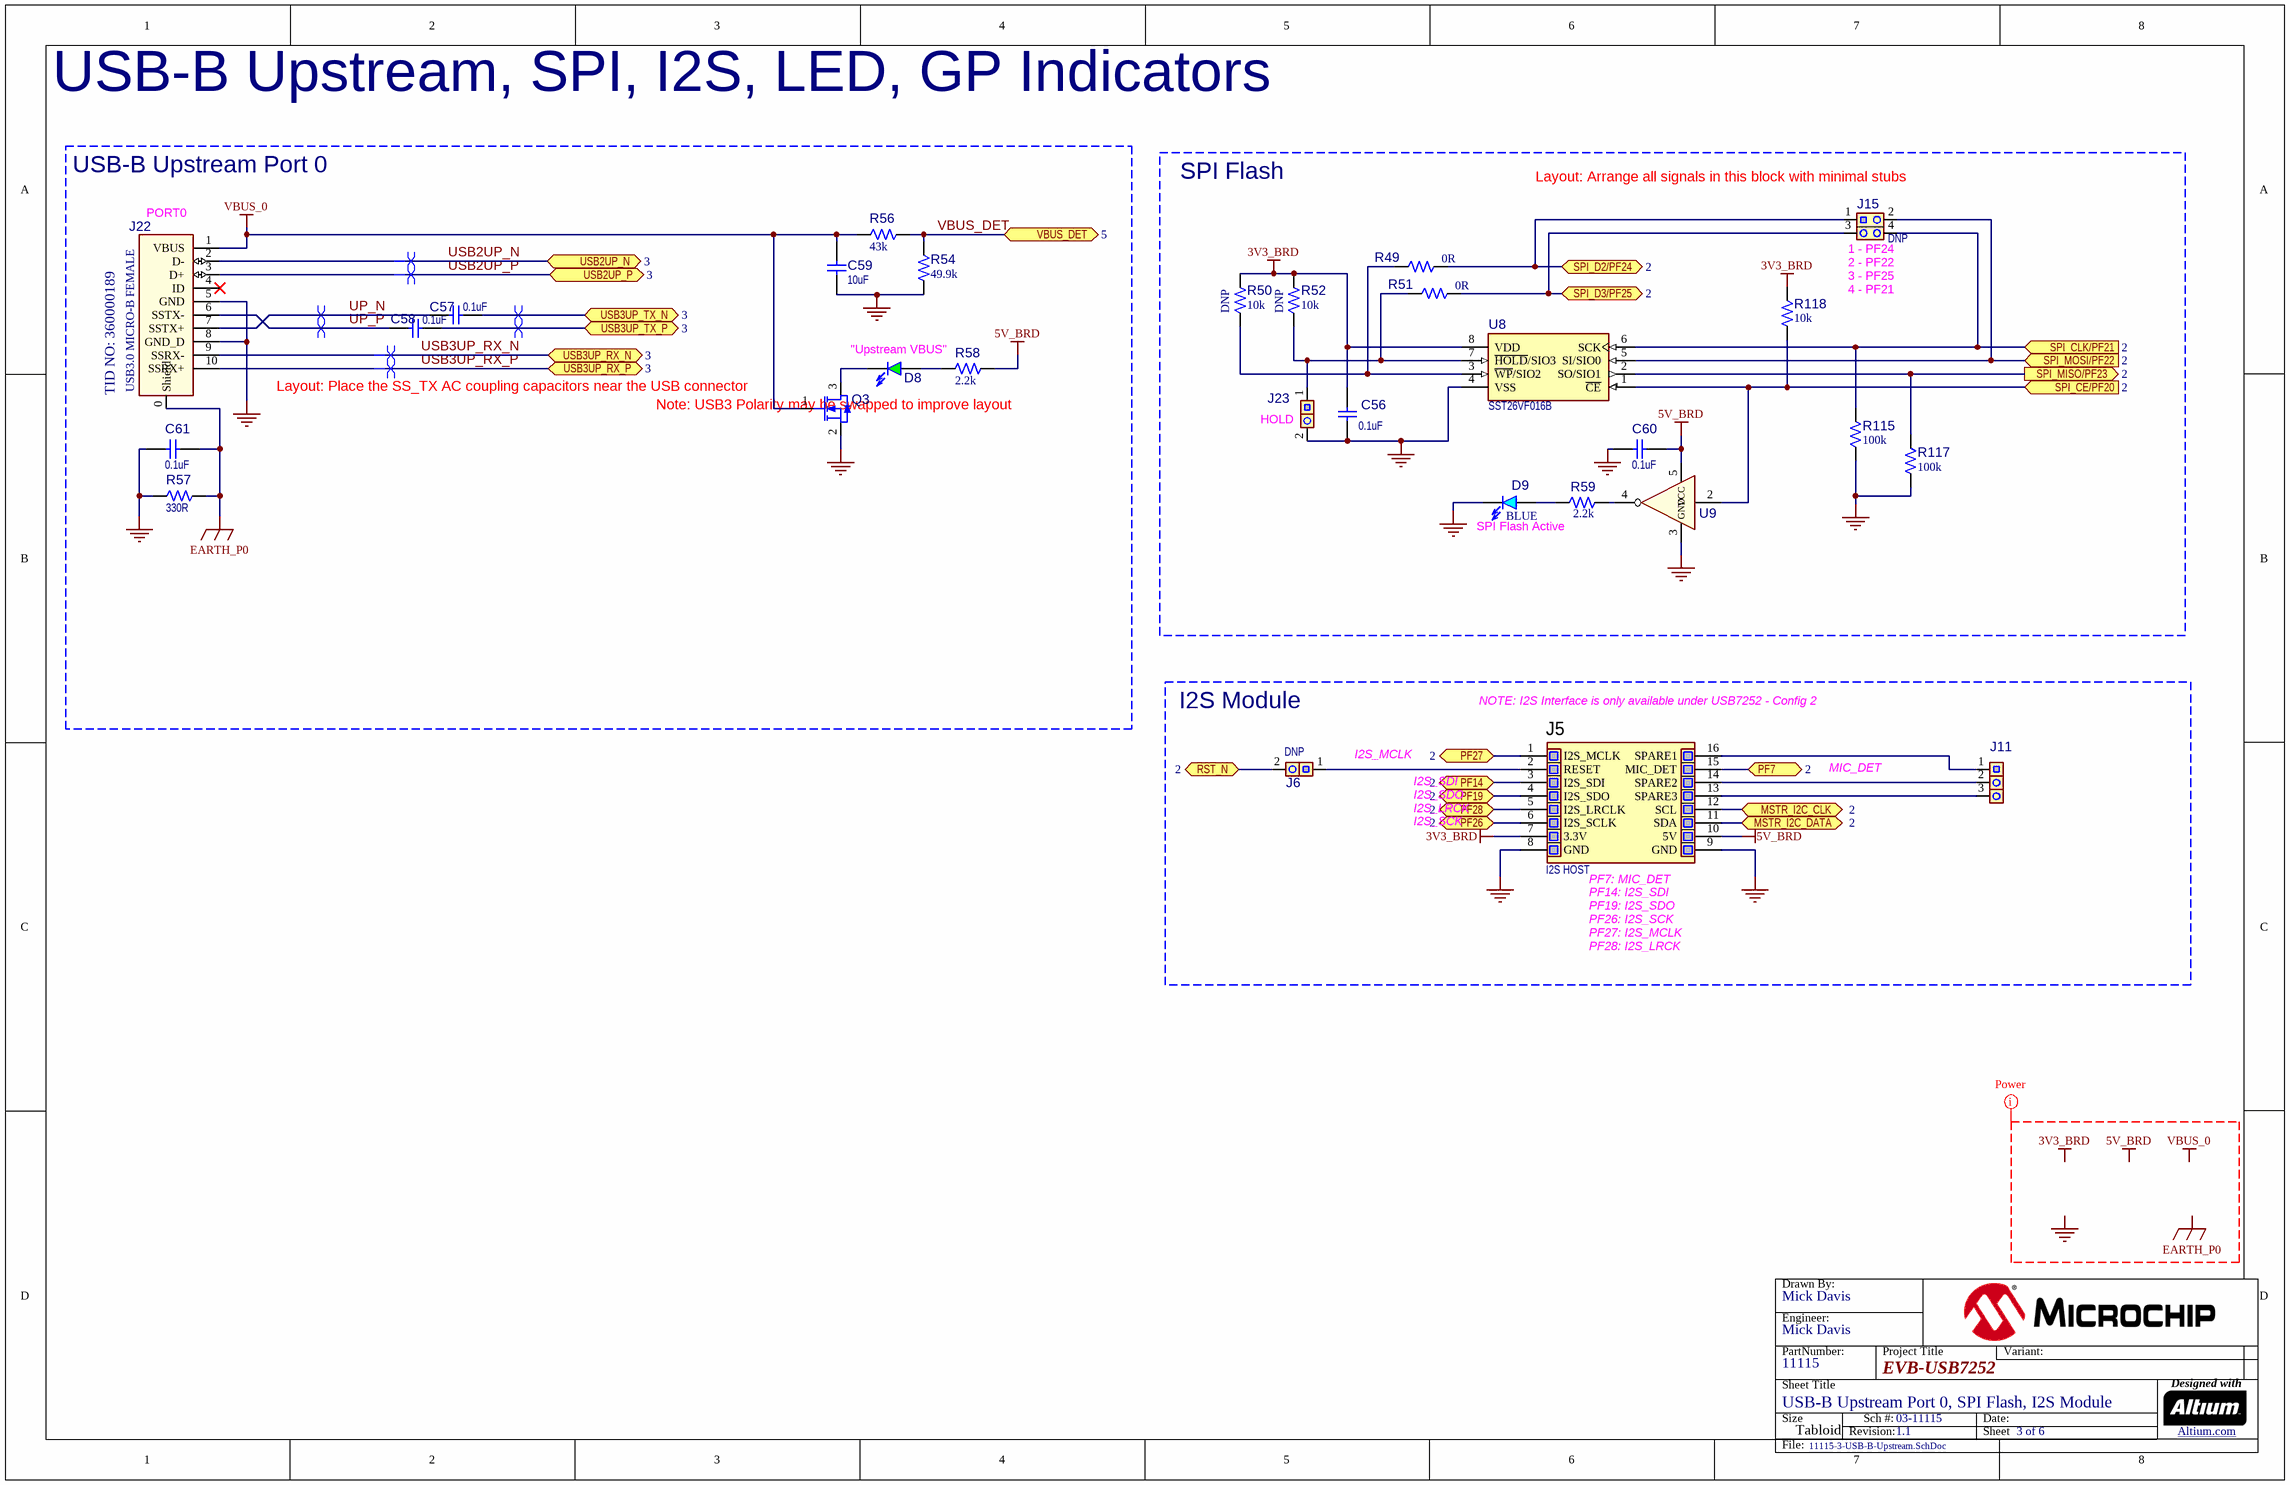
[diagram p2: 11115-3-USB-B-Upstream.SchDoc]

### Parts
(Parts that share a designator on the sheet are numbered #1, #2 ... from top to bottom, then left to right.)
?#3  (no value)  (graphical)
C56  value 0.1uF  [CAP_C_0402]  (hidden comment: Capacitor NP)
C57  value 0.1uF  [CAP_C_0402]  (hidden comment: Capacitor NP)
C58  value 0.1uF  [CAP_C_0402]  (hidden comment: Capacitor NP)
C59  value 10uF  [CAP_C_0805]  (hidden comment: Capacitor NP)
C60  value 0.1uF  [CAP_C_0402]  (hidden comment: Capacitor NP)
C61  value 0.1uF  [CAP_C_0402]  (hidden comment: Capacitor NP)
D8  LED_green  [LED_0603_GREEN]  (value not drawn)
D9  value BLUE  [LED_0603_Blue]  (hidden comment: LED_blue)
J5  value I2S HOST  [SOCKET_I2S_F_2.54_2x8_V_25.4x21_SMD]  (hidden comment: SOCKET I2S HOST)
J6  Populated: DNP  [HDR_M_2.54_1x2]  (hidden comment: Header 1x2)
J11  Header 1x3  [HDR_M_2.54_1x3]  (value not drawn)
J15  Populated: DNP  [HDR_M_2.54_2x2]  (hidden comment: Header 2x2)
J22  value USB3.0 MICRO-B FEMALE  [CON_USB3.0-B_RCPT_SMD_RA_HIR_ZX360D-B-10P]  (hidden comment: CON USB3.0 Micro B)
J23  Header 1x2  [HDR_M_2.54_1x2]  (value not drawn)
Q3  Transistor MOS-N GSD  [SOT-23-3]  (value not drawn)
R49  value 0R  [RES_C_0603]  (hidden comment: Resistor)
R50  value 10k  Populated: DNP  [RES_C_0603]  (hidden comment: Resistor)
R51  value 0R  [RES_C_0603]  (hidden comment: Resistor)
R52  value 10k  Populated: DNP  [RES_C_0603]  (hidden comment: Resistor)
R54  value 49.9k  [RES_C_0603]  (hidden comment: Resistor)
R56  value 43k  [RES_C_0603]  (hidden comment: Resistor)
R57  value 330R  [RES_C_0603]  (hidden comment: Resistor)
R58  value 2.2k  [RES_C_0603]  (hidden comment: Resistor)
R59  value 2.2k  [RES_C_0603]  (hidden comment: Resistor)
R115  value 100k  [RES_C_0603]  (hidden comment: Resistor)
R117  value 100k  [RES_C_0603]  (hidden comment: Resistor)
R118  value 10k  [RES_C_0603]  (hidden comment: Resistor)
U8  value SST26VF016B  [SOIJ-8]  (hidden comment: SST26VFXXX SOIC-8_WSON-8_SOIJ-8)
U9  74LVC1G14GW,125  [SC-70-5]  (value not drawn)

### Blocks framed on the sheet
USB-B Upstream Port 0: C57-C59 C61 D8 J22 Q3 R54 R56-R58
SPI Flash: C56 C60 D9 J15 J23 R49-R52 R59 R115 R117 R118 U8 U9
I2S Module: J5 J6 J11

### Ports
MSTR_I2C_CLK (bidir, see 2), MSTR_I2C_DATA (bidir, see 2), PF7 (bidir, see 2), PF14 (bidir, see 2), PF19 (bidir, see 2), PF26 (bidir, see 2), PF27 (bidir, see 2), PF28 (bidir, see 2), RST_N (bidir, see 2), SPI_CE/PF20 (in, see 2), SPI_CLK/PF21 (in, see 2), SPI_D2/PF24 (bidir, see 2), SPI_D3/PF25 (bidir, see 2), SPI_MISO/PF23 (out, see 2), SPI_MOSI/PF22 (in, see 2), USB2UP_N (bidir, see 3), USB2UP_P (bidir, see 3), USB3UP_RX_N (bidir, see 3), USB3UP_RX_P (bidir, see 3), USB3UP_TX_N (bidir, see 3), USB3UP_TX_P (bidir, see 3), VBUS_DET (bidir, see 5)

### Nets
3V3_BRD: C56.2 J5.7(3.3V) R50.2 R52.2 R118.2 U8.8(VDD)
5V_BRD: C60.1 J5.10(5V) R58.1 U9.5(VCC)
EARTH_P0: C61.2 J22.0(Shield) R57.2
GND: C56.1 C59.1 C60.2 C61.1 D9.2(K) J5.8(GND) J5.9(GND) J22.5(GND) J22.8(GND_D) J23.2 Q3.2(S) R54.1 R57.1 R115.1 R117.1 U8.4(VSS) U9.3(GND)
VBUS_0: C59.2 J22.1(VBUS) Q3.1(G) R56.1
MSTR_I2C_CLK: J5.12(SCL) ; port MSTR_I2C_CLK
MSTR_I2C_DATA: J5.11(SDA) ; port MSTR_I2C_DATA
PF7: J5.15(MIC_DET) ; port PF7
PF14: J5.3(I2S_SDI) ; port PF14
PF19: J5.4(I2S_SDO) ; port PF19
PF26: J5.6(I2S_SCLK) ; port PF26
PF27: J5.1(I2S_MCLK) ; port PF27
PF28: J5.5(I2S_LRCLK) ; port PF28
RST_N: J6.2 ; port RST_N
SPI_CE/PF20: R118.1 U8.1(~{CE}) U9.2(A) ; port SPI_CE/PF20
SPI_CLK/PF21: J15.4 R115.2 U8.6(SCK) ; port SPI_CLK/PF21
SPI_D2/PF24: J15.1 R49.2 ; port SPI_D2/PF24
SPI_D3/PF25: J15.3 R51.2 ; port SPI_D3/PF25
SPI_MISO/PF23: R117.2 U8.2(SO/SIO1) ; port SPI_MISO/PF23
SPI_MOSI/PF22: J15.2 U8.5(SI/SIO0) ; port SPI_MOSI/PF22
UP_N: C57.1 J22.7(SSTX+)
UP_P: C58.1 J22.6(SSTX-)
USB2UP_N: J22.2(D-) ; port USB2UP_N
USB2UP_P: J22.3(D+) ; port USB2UP_P
USB3UP_RX_N: J22.9(SSRX-) ; port USB3UP_RX_N
USB3UP_RX_P: J22.10(SSRX+) ; port USB3UP_RX_P
USB3UP_TX_N: C57.2 ; port USB3UP_TX_N
USB3UP_TX_P: C58.2 ; port USB3UP_TX_P
VBUS_DET: R54.2 R56.2 ; port VBUS_DET
NetD8_1: D8.1(A) R58.2
NetD8_2: D8.2(K) Q3.3(D)
NetD9_1: D9.1(A) R59.2
NetJ5_2: J5.2(RESET) J6.1
NetJ5_13: J5.13(SPARE3) J11.3
NetJ5_14: J5.14(SPARE2) J11.2
NetJ5_16: J5.16(SPARE1) J11.1
NetJ23_1: J23.1 R51.1 R52.1 U8.7(~{HOLD}/SIO3)
NetR49_1: R49.1 R50.1 U8.3(~{WP}/SIO2)
NetR59_1: R59.1 U9.4(Y)

Not connected (* = marked no-connect by the designer): J22 4(ID)*; U9 1(NC)

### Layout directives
net class Power: 3V3_BRD, 5V_BRD, EARTH_P0, GND, VBUS_0
differential pair; net class USB3.: UP_N, UP_P, USB2UP_N, USB2UP_P, USB3UP_RX_N, USB3UP_RX_P, USB3UP_TX_N, USB3UP_TX_P

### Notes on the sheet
- USB-B Upstream, SPI, I2S, LED, GP Indicators
- (near J22) PORT0
- (near J15) Layout: Arrange all signals in this block with minimal stubs
- (near J15) 1 - PF24
- (near J15) 2 - PF22
- (near J15) 3 - PF25
- 4 - PF21
- "Upstream VBUS"
- TID NO: 360000189
- Layout: Place the SS_TX AC coupling capacitors near the USB connector
- Note: USB3 Polarity may be swapped to improve layout
- (near J23) HOLD
- SPI Flash Active
- (near J5) NOTE: I2S Interface is only available under USB7252 - Config 2
- (near J6) I2S_MCLK
- I2S_SDI
- I2S_SCK
- I2S_LRCK
- I2S_SDO
- MIC_DET
- (near J5) PF14: I2S_SDI
- (near J5) PF7: MIC_DET
- (near J5) PF19: I2S_SDO
- PF26: I2S_SCK
- PF27: I2S_MCLK
- PF28: I2S_LRCK
- Labels drawn without touching a wire or pin: 3V3_BRD, 5V_BRD, EARTH_P0, GND, VBUS_0

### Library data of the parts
?#3 = Title Block Tabloid
C56 C60 = CAP1337: as C21 on sheet 11115-2-USB7252
C57 C58 C61 = CAP1337: Capacitor; Manufacturer 1: TDK Corporation; Manufacturer Part Number 1: CGA2B3X7R1V104K050BB; Voltage: 35V; Description_: CAP CER 0.1uF 35V 10% X7R SMD 0402; Dev Tools Status: Production; Tolerance: 10%; Temperature Coeffcient: X7R; Type: Ceramic; Owner: Sam Charles; Populated: YES
C59 = CAP0373: Capacitor; Manufacturer 1: Wurth Electronics Inc; Manufacturer Part Number 1: 885012107014; Voltage: 16V; Description_: CAP CER 10uF 16V 10% X5R SMD 0805; Dev Tools Status: Production; Tolerance: 10%; Temperature Coeffcient: X5R; Type: Ceramic; Populated: Yes
D8 = DIODE1155: LED; Manufacturer 1: Lite-On Inc; Manufacturer Part Number 1: LTST-C191KGKT; Value: GREEN; Description_: DIO LED GREEN 2V 30mA 35mcd Clear SMD 0603; Dev Tools Status: Production; Type: LED Single; Forward Current: 30mA; Power: 75mW; Reverse Voltage: 5V; Owner: Tad Ahlvers; Populated: YES
D9 = DIODE1056: LED; Manufacturer 1: Lite-On; Manufacturer Part Number 1: LTST-C193TBKT-5A; Description_: DIO LED BLUE 2.8V 20mA 15mcd Clear SMD 0603; Type: LED Single; Forward Current: 20mA; Power: 76mW; Reverse Current: 10uA; Reverse Voltage: 5V; Owner: Tad Ahlvers; Populated: YES; Dev Tools Status: Production
J5 = SKT1105: Manufacturer 1: 3M; Manufacturer Part Number 1: 963108-2000-AR-PR; Description_: SOCKET I2S HOST DIP 16 TH; Dev Tools Status: Design; Owner: Sam Charles; Populated: YES
J6 = CON1108: Manufacturer 1: FCI; Manufacturer Part Number 1: 77311-118-02LF; Value: HDR-2.54 Male 1x2; Description_: CON HDR-2.54 Male 1x2 Gold 5.84MH TH VERT; Dev Tools Status: Production; Owner: Bogdan P (M91398)
J11 = CON1105: as J16 on sheet 11115-2-USB7252
J15 = CON0464: Manufacturer 1: Samtec; Manufacturer Part Number 1: TSW-102-07-G-D; Value: HDR-2.54 Male 2x2; Description_: CON HDR-2.54 Male 2x2 Gold 5.84MH TH VERT; Dev Tools Status: Production
J22 = CON1341: Connector USB; Manufacturer 1: Hirose Electric Co Ltd; Manufacturer Part Number 1: ZX360D-B-10P; Description_: CON USB3.0 MICRO-B FEMALE SMD R/A; Dev Tools Status: Design; Owner: Randolph Sobrepena; Voltage: 30V; Current: 1.8A; Populated: YES
J23 = CON1108: as J9 on sheet 11115-2-USB7252
Q3 = TRA1102: Transistor MOS; Manufacturer 1: Diodes Inc; Value: 2N7002-7-F; Description_: TRANS FET N-CH 2N7002-7-F 60V 170mA 370mW SOT-23-3; Dev Tools Status: Production; Type: FET; Current: 170mA; Drain to Source Voltage: 60V; Gate to Source Voltage: 20V; Power: 370mW; Owner: Adrian M (M91404); Populated: YES
R49 R51 = RSMT0001: as R36 on sheet 11115-2-USB7252
R50 R52 = RSMT0625: Manufacturer 1: ROHM; Manufacturer Part Number 1: MCR03EZPFX1002; Tolerance: 1%; Description_: RES TKF 10k 1% 1/10W SMD 0603; Voltage: 75V; Temperature Coeffcient: 100ppm/C; Power: 1/10W; Dev Tools Status: Production
R54 = RSMT0383: Manufacturer 1: Panasonic; Manufacturer Part Number 1: ERJ-3EKF4992V; Tolerance: 1%; Description_: RES TKF 49.9k 1% 1/10W SMD 0603; Dev Tools Status: Production; Voltage: 75V; Temperature Coeffcient: 100ppm/C; Power: 1/10W; Populated: Yes
R56 = RSMT0665: Manufacturer 1: Yageo; Manufacturer Part Number 1: 9C06031A4302FKHFT; Tolerance: 1%; Description_: RES TKF 43k 1% 1/10W SMD 0603; Dev Tools Status: Production; Voltage: 50V; Temperature Coeffcient: 100ppm/C; Power: 1/10W; Populated: Yes
R57 = RSMT0626: Manufacturer 1: Panasonic; Manufacturer Part Number 1: ERJ-3EKF3300V; Tolerance: 1%; Description_: RES TKF 330R 1% 1/10W SMD 0603; Dev Tools Status: Production; Voltage: 75V; Temperature Coeffcient: 100ppm/C; Power: 1/10W; Populated: Yes
R58 R59 = RES1130: Manufacturer 1: Panasonic; Manufacturer Part Number 1: ERJ-3EKF2201V; Tolerance: 1%; Description_: RES TKF 2.2k 1% 1/10W SMD 0603; Voltage: 75V; Temperature Coeffcient: 100ppm/C; Power: 1/10W; Owner: Bogdan P (M91398); Populated: Yes
R115 R117 = RSMT0215: as R120 on sheet 11115-2-USB7252
R118 = RSMT0625: as R21 on sheet 11115-2-USB7252
U8 = MIC6476: SQI Serial Flash; Manufacturer 1: Microchip Technology; Manufacturer Part Number 1: SST26VF016B-104I/SM; Description_: MCHP MEMORY SERIAL FLASH 16M 104MHz SST26VF016B-104I/SM SOIJ-8; MAPS Description: 16Mb 2.7V TO 3.6V SQI Flash Memory; Dev Tools Status: Production; Owner: Sorin Stanoaia; MPC: S01047C3XA23; PackingMedia: TUBE; TempRange: -40C to +85C; Stage: REL; LeadCount: 8; PackageWidth: .208in; ForceMinOrderQtyMult: False; MinOrderQty: 0; LeadContent: Pb-FREE; Busmodes: SPI,SDI,SQI; OpVoltMin: 2.3; OpVoltMax: 3.6; MaxClockFreq: 104 MHz; PageSize_B: 256; Endurance: 100,000; Populated: YES
U9 = IC1251: as U11 on sheet 11115-2-USB7252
